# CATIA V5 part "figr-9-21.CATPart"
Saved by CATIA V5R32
Part number: Part3
Bounding box of the stored display mesh (mm): x -112 to 0, y -101.683 to 104.654, z -80.304 to 44.557
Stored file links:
  D:\PROJECTS\Project 2022\CATIA V5 6R 2022\Resources\Part Files\c09_catia_v5_6r2022_prt\c09_catia_v5_6r2022_prt\figr-9-21.CATPart
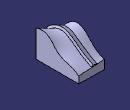
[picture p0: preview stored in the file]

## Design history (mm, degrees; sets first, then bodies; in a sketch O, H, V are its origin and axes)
Set1
  Plane1: type Offset, RefPlane yz-plane, Offset -112
  Plane2: type Offset, RefPlane yz-plane, Offset -63
  Plane3: type Normal, Curve Sketch4, RefPoint vertex of Sketch4
Body1 (main body)
  Sketch1 on yz-plane, origin (0, 0, 0), H (0, 1, 0), V (0, 0, 1)
    spline S1 through (-92.6897, 40.1119) (-30, 30) (10, -10) (60, -30) (97.3103, -50.3041)
    line L1 (97.3103, -50.3041) -> (97.3103, -80.3041)
    line L2 (97.3103, -80.3041) -> (-92.6897, -80.3041)
    line L3 (-92.6897, -80.3041) -> (-92.6897, 40.1119)
    point P3 (-92.6897, 40.1119)
    point P4 (97.3103, -50.3041)
    point P5 (-92.6897, 40.1119)
    point P6 (97.3103, -50.3041)
    vertical: L1 V, L3 V
    horizontal: L2 H
    coincidence: P5 P3, P6 P4
  Sketch2 on Plane1, origin (-112, 0, 0), H (0, 1, 0), V (0, 0, 1)
    spline S1 through (-90, -30) (-70, 10) (-20, 40) (40, 0) (100, -40)
    line L1 (100, -40) -> (100, -80)
    line L2 (100, -80) -> (-90, -80)
    line L3 (-90, -80) -> (-90, -30)
    point P3 (-90, -30)
    point P4 (100, -40)
    point P5 (40, 0)
    point P6 (-90, -30)
    point P7 (100, -40)
    coincidence: P5 H, P6 P3, P7 P4
    vertical: L1 V, L3 V
    horizontal: L2 H
  Loft1: Sections (Sketch1; Sketch2)
  Sketch3 on Plane3, origin (0, -40.1726, -44.9298), H (1, 0, 0), V (0, -0.7455, 0.6665)
    point P1 (-63, 68.4187)
    line L1 (-63, 68.4187) -> (-75.2117, 62.4925)
    line L2 (-75.2117, 62.4925) -> (-79.6266, 71.5898)
    line L3 (-79.6266, 71.5898) -> (-57.1205, 82.5119)
    line L4 (-57.1205, 82.5119) -> (-52.7056, 73.4145)
    point P5 (-52.7056, 73.4145)
    line L5 (-52.7056, 73.4145) -> (-63, 68.4187)
    reference projected point E1 (-63, 68.4187) from vertex of Sketch4
    perpendicularity: L2 L1
    parallelism: L3 L1, L4 L2, L5 L1
    coincidence: P5 L1, P1 E1
  Sketch4 on Plane2, origin (-63, 0, 0), H (0, 1, 0), V (0, 0, 1)
    intersected curve E1 from face of Loft1
  Rib1: profile Sketch3, centre curve Sketch4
